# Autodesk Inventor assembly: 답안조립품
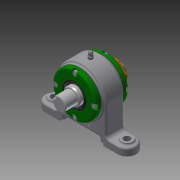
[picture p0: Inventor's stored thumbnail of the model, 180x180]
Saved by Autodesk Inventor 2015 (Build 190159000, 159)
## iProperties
Created: 2019-05
Part Number: 답안조립품
Document SubType Name: Assembly
Designer: now
Author: now
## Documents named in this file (13)
- C:\Users\now\Desktop\490504V1045\490504V1045\답안조립품.iam
- C:\Users\now\Desktop\490504V1045\490504V1045\개스킷.ipt
- C:\Users\now\Desktop\490504V1045\490504V1045\그리스니플 M6.ipt
- 그리스니플  M6.ipt
- C:\Users\now\Desktop\490504V1045\490504V1045\그리스니플개스킷.ipt
- C:\Users\now\Desktop\490504V1045\490504V1045\베어링너트.ipt
- C:\Users\now\Desktop\490504V1045\490504V1045\본체.ipt
- C:\Users\now\Desktop\490504V1045\490504V1045\볼트 M4.ipt
- C:\Users\now\Desktop\490504V1045\490504V1045\앵귤러 볼 베어링 7205.ipt
- C:\Users\now\Desktop\490504V1045\490504V1045\오일 실 28 40 5 B.ipt
- C:\Users\now\Desktop\490504V1045\490504V1045\축.ipt
- C:\Users\now\Desktop\490504V1045\490504V1045\칼라.ipt
- C:\Users\now\Desktop\490504V1045\490504V1045\커버.ipt
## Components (4 placed, 3 different names)
1. 개스킷:1
2. 그리스니플  M6:1
3. 그리스니플개스킷:1
4. 개스킷:2
